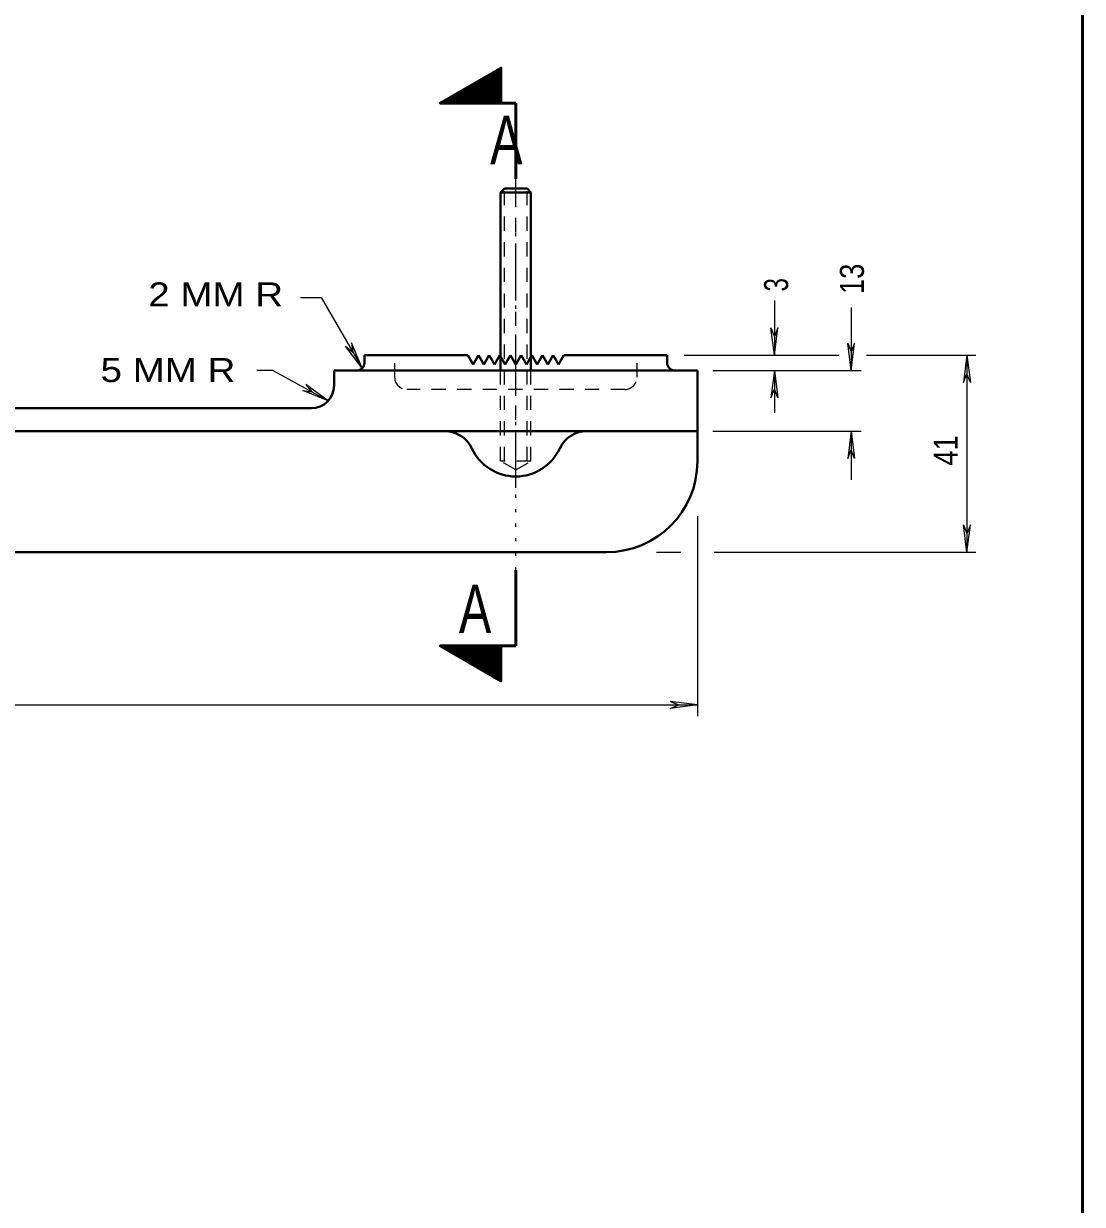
# Model space of a CAD drawing. Extents: x 312583 to 312854, y 144419 to 144597.
# Drawn here: x 312736.75 to 312770.25, y 144521.88 to 144559.26 of the extents above; entities that cross this region are included whole.
import ezdxf
from ezdxf.enums import TextEntityAlignment as Align

# ---------------------------------------------------------------- set-up
doc = ezdxf.new("R2010")
doc.units = 0
doc.header["$LTSCALE"] = 0.3
for name, pattern in [('DOTTED', [1.5, 0.3, -1.2]), ('LONG_DASH_SHORT_DASH', [9.9, 6, -1.2, 1.5, -1.2]), ('SHORT_DASHED', [2.7, 1.5, -1.2])]:
    doc.linetypes.add(name, pattern=pattern)
doc.layers.add('1', color=7, linetype='Continuous', lineweight=40)
doc.layers.add('2', color=7, linetype='Continuous', lineweight=13)

msp = doc.modelspace()

# ---------------------------------------------------------------- linework, layer by layer
at = {"layer": '1', "lineweight": 53}
for p, q in [((312770.2547, 144423.0156), (312770.2547, 144585.0846)), ((312751.851, 144556.7382), (312752.3263, 144556.7382)), ((312752.3263, 144554.3462), (312752.3263, 144556.7382)), ((312752.3263, 144541.9492), (312752.3263, 144539.5572)), ((312751.851, 144539.5572), (312752.3263, 144539.5572))]:
    msp.add_line(p, q, dxfattribs=at)
at = {"layer": '1', "lineweight": 35}
for p, q in [((312751.851, 144557.4358), (312751.6747, 144557.7425)), ((312751.851, 144557.4818), (312751.69, 144557.7502)), ((312751.851, 144557.5278), (312751.713, 144557.7655)), ((312751.851, 144557.5815), (312751.736, 144557.7732)), ((312751.851, 144557.6198), (312751.7513, 144557.7885)), ((312751.851, 144557.6735), (312751.7743, 144557.7962)), ((312751.851, 144557.7195), (312751.7973, 144557.8115)), ((312751.851, 144557.7732), (312751.8127, 144557.8268)), ((312751.851, 144557.8192), (312751.8357, 144557.8345)), ((312751.368, 144556.7382), (312751.0077, 144557.3592)), ((312751.391, 144556.7382), (312751.0307, 144557.3668)), ((312751.414, 144556.7382), (312751.046, 144557.3822)), ((312751.4447, 144556.7458), (312751.069, 144557.3898)), ((312751.4753, 144556.7382), (312751.092, 144557.4052)), ((312751.4983, 144556.7382), (312751.1073, 144557.4128)), ((312751.529, 144556.7382), (312751.1303, 144557.4282)), ((312751.5597, 144556.7382), (312751.1533, 144557.4435)), ((312751.5827, 144556.7382), (312751.1763, 144557.4512)), ((312751.6133, 144556.7382), (312751.1917, 144557.4665)), ((312751.644, 144556.7382), (312751.2147, 144557.4818)), ((312751.667, 144556.7458), (312751.2377, 144557.4895)), ((312751.6977, 144556.7458), (312751.253, 144557.5048)), ((312751.7207, 144556.7382), (312751.276, 144557.5125)), ((312751.7513, 144556.7382), (312751.299, 144557.5278)), ((312751.7743, 144556.7382), (312751.3143, 144557.5355)), ((312751.805, 144556.7382), (312751.3373, 144557.5508)), ((312751.8357, 144556.7382), (312751.3603, 144557.5585)), ((312751.851, 144556.7612), (312751.3757, 144557.5738)), ((312751.851, 144556.8148), (312751.4063, 144557.5815)), ((312751.851, 144556.8532), (312751.4217, 144557.5968)), ((312751.851, 144556.9068), (312751.4447, 144557.6045)), ((312751.851, 144556.9528), (312751.4677, 144557.6198)), ((312751.851, 144556.9988), (312751.483, 144557.6352)), ((312751.851, 144557.0448), (312751.506, 144557.6428)), ((312751.851, 144557.0985), (312751.529, 144557.6582)), ((312751.851, 144557.1445), (312751.5443, 144557.6735)), ((312751.851, 144557.1905), (312751.5673, 144557.6812)), ((312751.851, 144557.2442), (312751.5827, 144557.6965)), ((312751.851, 144557.2902), (312751.6057, 144557.7042)), ((312751.851, 144557.3362), (312751.6287, 144557.7195)), ((312751.851, 144557.3898), (312751.644, 144557.7272)), ((312750.5093, 144556.7382), (312750.3637, 144556.9912)), ((312750.5323, 144556.7382), (312750.379, 144556.9988)), ((312750.563, 144556.7382), (312750.4097, 144557.0142)), ((312750.586, 144556.7382), (312750.425, 144557.0218)), ((312750.6167, 144556.7382), (312750.448, 144557.0372)), ((312750.6473, 144556.7382), (312750.471, 144557.0448)), ((312750.6703, 144556.7382), (312750.4863, 144557.0602)), ((312750.701, 144556.7382), (312750.5093, 144557.0678)), ((312750.724, 144556.7382), (312750.5323, 144557.0832)), ((312750.7547, 144556.7382), (312750.5477, 144557.0985)), ((312750.7777, 144556.7382), (312750.5707, 144557.1062)), ((312750.8083, 144556.7382), (312750.5937, 144557.1215)), ((312750.839, 144556.7382), (312750.609, 144557.1368)), ((312750.8697, 144556.7382), (312750.632, 144557.1445)), ((312750.8927, 144556.7382), (312750.655, 144557.1598)), ((312750.9157, 144556.7382), (312750.678, 144557.1675)), ((312750.9463, 144556.7382), (312750.6933, 144557.1828)), ((312750.977, 144556.7382), (312750.7163, 144557.1905)), ((312751, 144556.7382), (312750.7393, 144557.2058)), ((312751.0307, 144556.7382), (312750.7547, 144557.2135)), ((312751.0613, 144556.7382), (312750.7777, 144557.2288)), ((312751.0843, 144556.7382), (312750.8007, 144557.2365)), ((312751.115, 144556.7382), (312750.816, 144557.2518)), ((312751.1457, 144556.7382), (312750.839, 144557.2595)), ((312751.1687, 144556.7382), (312750.862, 144557.2748)), ((312751.1993, 144556.7458), (312750.8773, 144557.2902)), ((312751.2223, 144556.7382), (312750.908, 144557.2978)), ((312751.253, 144556.7382), (312750.9233, 144557.3132)), ((312751.276, 144556.7382), (312750.9463, 144557.3208)), ((312751.3067, 144556.7382), (312750.9693, 144557.3362)), ((312751.3373, 144556.7382), (312750.9847, 144557.3438)), ((312749.9497, 144556.7382), (312749.9497, 144556.7535)), ((312749.9803, 144556.7382), (312749.9727, 144556.7612)), ((312750.011, 144556.7382), (312749.988, 144556.7765)), ((312750.034, 144556.7382), (312750.011, 144556.7842)), ((312750.0647, 144556.7382), (312750.034, 144556.7995)), ((312750.0877, 144556.7382), (312750.0493, 144556.8072)), ((312750.1183, 144556.7382), (312750.0723, 144556.8225)), ((312750.149, 144556.7382), (312750.0953, 144556.8302)), ((312750.1797, 144556.7382), (312750.1107, 144556.8455)), ((312750.2027, 144556.7382), (312750.1337, 144556.8532)), ((312750.2257, 144556.7382), (312750.1567, 144556.8685)), ((312750.2563, 144556.7382), (312750.1797, 144556.8762)), ((312750.2793, 144556.7382), (312750.195, 144556.8915)), ((312750.31, 144556.7382), (312750.218, 144556.9068)), ((312750.3407, 144556.7382), (312750.241, 144556.9145)), ((312750.3713, 144556.7382), (312750.2563, 144556.9298)), ((312750.3943, 144556.7382), (312750.2793, 144556.9452)), ((312750.425, 144556.7382), (312750.3023, 144556.9528)), ((312750.448, 144556.7382), (312750.3177, 144556.9682)), ((312750.4787, 144556.7382), (312750.3407, 144556.9758)), ((312749.9497, 144539.5572), (312749.9497, 144539.5418)), ((312749.9803, 144539.5572), (312749.9727, 144539.5342)), ((312750.011, 144539.5572), (312749.988, 144539.5188)), ((312750.034, 144539.5572), (312750.011, 144539.5112)), ((312750.0647, 144539.5572), (312750.034, 144539.4958)), ((312750.0877, 144539.5572), (312750.0493, 144539.4882)), ((312750.1183, 144539.5572), (312750.0723, 144539.4728)), ((312750.149, 144539.5572), (312750.0953, 144539.4652)), ((312750.1797, 144539.5572), (312750.1107, 144539.4498)), ((312750.2027, 144539.5572), (312750.1337, 144539.4422)), ((312750.2257, 144539.5572), (312750.1567, 144539.4268)), ((312750.2563, 144539.5572), (312750.1797, 144539.4192)), ((312750.2793, 144539.5572), (312750.195, 144539.4038)), ((312750.31, 144539.5572), (312750.218, 144539.3885)), ((312750.3407, 144539.5572), (312750.241, 144539.3808)), ((312750.3713, 144539.5572), (312750.2563, 144539.3655)), ((312750.3943, 144539.5572), (312750.2793, 144539.3502)), ((312750.425, 144539.5572), (312750.3023, 144539.3425)), ((312750.448, 144539.5572), (312750.3177, 144539.3272)), ((312750.4787, 144539.5572), (312750.3407, 144539.3195)), ((312750.5093, 144539.5572), (312750.3637, 144539.3042)), ((312750.5323, 144539.5572), (312750.379, 144539.2965)), ((312750.563, 144539.5572), (312750.4097, 144539.2812)), ((312750.586, 144539.5572), (312750.425, 144539.2735)), ((312750.6167, 144539.5572), (312750.448, 144539.2582)), ((312750.6473, 144539.5572), (312750.471, 144539.2505)), ((312750.6703, 144539.5572), (312750.4863, 144539.2352)), ((312750.701, 144539.5572), (312750.5093, 144539.2275)), ((312750.724, 144539.5572), (312750.5323, 144539.2122)), ((312750.7547, 144539.5572), (312750.5477, 144539.1968)), ((312750.7777, 144539.5572), (312750.5707, 144539.1892)), ((312750.8083, 144539.5572), (312750.5937, 144539.1738)), ((312750.839, 144539.5572), (312750.609, 144539.1585)), ((312750.8697, 144539.5572), (312750.632, 144539.1508)), ((312750.8927, 144539.5572), (312750.655, 144539.1355)), ((312750.9157, 144539.5572), (312750.678, 144539.1278)), ((312750.9463, 144539.5572), (312750.6933, 144539.1125)), ((312750.977, 144539.5572), (312750.7163, 144539.1048)), ((312751, 144539.5572), (312750.7393, 144539.0895)), ((312751.0307, 144539.5572), (312750.7547, 144539.0818)), ((312751.0613, 144539.5572), (312750.7777, 144539.0665)), ((312751.0843, 144539.5572), (312750.8007, 144539.0588)), ((312751.115, 144539.5572), (312750.816, 144539.0435)), ((312751.1457, 144539.5572), (312750.839, 144539.0358)), ((312751.1687, 144539.5572), (312750.862, 144539.0205)), ((312751.1993, 144539.5495), (312750.8773, 144539.0052)), ((312751.2223, 144539.5572), (312750.908, 144538.9975)), ((312751.253, 144539.5572), (312750.9233, 144538.9822)), ((312751.276, 144539.5572), (312750.9463, 144538.9745)), ((312751.3067, 144539.5572), (312750.9693, 144538.9592)), ((312751.3373, 144539.5572), (312750.9847, 144538.9515)), ((312751.368, 144539.5572), (312751.0077, 144538.9362)), ((312751.391, 144539.5572), (312751.0307, 144538.9285)), ((312751.414, 144539.5572), (312751.046, 144538.9132)), ((312751.4447, 144539.5495), (312751.069, 144538.9055)), ((312751.4753, 144539.5572), (312751.092, 144538.8902)), ((312751.4983, 144539.5572), (312751.1073, 144538.8825)), ((312751.529, 144539.5572), (312751.1303, 144538.8672)), ((312751.5597, 144539.5572), (312751.1533, 144538.8518)), ((312751.5827, 144539.5572), (312751.1763, 144538.8442)), ((312751.6133, 144539.5572), (312751.1917, 144538.8288)), ((312751.644, 144539.5572), (312751.2147, 144538.8135)), ((312751.667, 144539.5495), (312751.2377, 144538.8058)), ((312751.6977, 144539.5495), (312751.253, 144538.7905)), ((312751.7207, 144539.5572), (312751.276, 144538.7828)), ((312751.7513, 144539.5572), (312751.299, 144538.7675)), ((312751.7743, 144539.5572), (312751.3143, 144538.7598)), ((312751.805, 144539.5572), (312751.3373, 144538.7445)), ((312751.8357, 144539.5572), (312751.3603, 144538.7368)), ((312751.851, 144539.5342), (312751.3757, 144538.7215)), ((312751.851, 144539.4805), (312751.4063, 144538.7138)), ((312751.851, 144539.4422), (312751.4217, 144538.6985)), ((312751.851, 144539.3885), (312751.4447, 144538.6908)), ((312751.851, 144539.3425), (312751.4677, 144538.6755)), ((312751.851, 144539.2965), (312751.483, 144538.6602)), ((312751.851, 144539.2505), (312751.506, 144538.6525)), ((312751.851, 144539.1968), (312751.529, 144538.6372)), ((312751.851, 144539.1508), (312751.5443, 144538.6218)), ((312751.851, 144539.1048), (312751.5673, 144538.6142)), ((312751.851, 144539.0512), (312751.5827, 144538.5988)), ((312751.851, 144539.0052), (312751.6057, 144538.5912)), ((312751.851, 144538.9592), (312751.6287, 144538.5758)), ((312751.851, 144538.9055), (312751.644, 144538.5682)), ((312751.851, 144538.8595), (312751.6747, 144538.5528)), ((312751.851, 144538.8135), (312751.69, 144538.5452)), ((312751.851, 144538.7675), (312751.713, 144538.5298)), ((312751.851, 144538.7138), (312751.736, 144538.5222)), ((312751.851, 144538.6755), (312751.7513, 144538.5068)), ((312751.851, 144538.6218), (312751.7743, 144538.4992)), ((312751.851, 144538.5758), (312751.7973, 144538.4838)), ((312751.851, 144538.5222), (312751.8127, 144538.4685)), ((312751.851, 144538.4762), (312751.8357, 144538.4608))]:
    msp.add_line(p, q, dxfattribs=at)
at = {"layer": '1', "linetype": 'DOTTED', "lineweight": 13}
msp.add_line((312752.3263, 144541.9492), (312752.3263, 144554.8215), dxfattribs=at)
at = {"layer": '1', "linetype": 'LONG_DASH_SHORT_DASH', "lineweight": 13}
msp.add_line((312752.3263, 144544.5558), (312752.3263, 144554.5378), dxfattribs=at)
at = {"layer": '1'}
for p, q in [((312751.8433, 144553.9092), (312751.966, 144554.0318)), ((312752.679, 144554.0318), (312751.966, 144554.0318)), ((312752.8017, 144553.9092), (312752.679, 144554.0318)), ((312752.8017, 144553.9092), (312751.8433, 144553.9092)), ((312751.8433, 144548.2742), (312751.8433, 144553.9092)), ((312752.8017, 144548.2742), (312752.8017, 144553.9092)), ((312747.5347, 144548.5195), (312747.5347, 144548.7572)), ((312750.8083, 144548.7572), (312747.5347, 144548.7572)), ((312750.977, 144548.4658), (312750.8083, 144548.7572)), ((312750.977, 144548.4658), (312751.1457, 144548.7572)), ((312751.3143, 144548.4658), (312751.1457, 144548.7572)), ((312751.3143, 144548.4658), (312751.483, 144548.7572)), ((312751.6517, 144548.4658), (312751.483, 144548.7572)), ((312751.6517, 144548.4658), (312751.8203, 144548.7572)), ((312751.989, 144548.4658), (312751.8203, 144548.7572)), ((312751.989, 144548.4658), (312752.1577, 144548.7572)), ((312752.3263, 144548.4658), (312752.1577, 144548.7572)), ((312752.3263, 144548.4658), (312752.495, 144548.7572)), ((312752.6637, 144548.4658), (312752.495, 144548.7572)), ((312752.6637, 144548.4658), (312752.8323, 144548.7572)), ((312753.001, 144548.4658), (312752.8323, 144548.7572)), ((312753.001, 144548.4658), (312753.1697, 144548.7572)), ((312753.3383, 144548.4658), (312753.1697, 144548.7572)), ((312753.3383, 144548.4658), (312753.507, 144548.7572)), ((312753.6757, 144548.4658), (312753.507, 144548.7572)), ((312753.6757, 144548.4658), (312753.8443, 144548.7572)), ((312757.118, 144548.7572), (312753.8443, 144548.7572)), ((312757.118, 144548.5195), (312757.118, 144548.7572)), ((312746.5763, 144547.7988), (312746.5763, 144548.2742)), ((312758.0763, 144548.2742), (312746.5763, 144548.2742)), ((312758.0763, 144545.3992), (312758.0763, 144548.2742)), ((312692.9097, 144547.0782), (312745.8557, 144547.0782)), ((312692.9097, 144546.3575), (312758.0763, 144546.3575)), ((312695.7847, 144542.5242), (312755.2013, 144542.5242))]:
    msp.add_line(p, q, dxfattribs=at)
at = {"layer": '1', "linetype": 'SHORT_DASHED', "lineweight": 25}
for p, q in [((312751.966, 144545.4068), (312751.966, 144554.0318)), ((312752.679, 144545.4068), (312752.679, 144554.0318)), ((312748.493, 144548.0595), (312748.493, 144548.7572)), ((312756.1597, 144548.0595), (312756.1597, 144548.7572)), ((312751.8433, 144545.4068), (312751.8433, 144548.2742)), ((312752.8017, 144545.4068), (312752.8017, 144548.2742)), ((312755.7763, 144547.6762), (312748.8763, 144547.6762)), ((312752.8017, 144545.4068), (312751.8433, 144545.4068)), ((312752.3263, 144545.1308), (312751.8433, 144545.4068)), ((312752.3263, 144545.1308), (312752.8017, 144545.4068))]:
    msp.add_line(p, q, dxfattribs=at)
at = {"layer": '1', "lineweight": 53}
for points in [[(312751.851, 144556.7382), (312751.851, 144557.8498), (312749.9343, 144556.7382)], [(312751.851, 144539.5572), (312751.851, 144538.4455), (312749.9343, 144539.5572)]]:
    msp.add_lwpolyline(points, close=True, dxfattribs=at)
at = {"layer": '1'}
for centre, radius, start, end in [((312747.2913, 144548.5137), 0.2396, 270, 0), ((312757.3538, 144548.5137), 0.2396, 180, 270), ((312745.8538, 144547.7969), 0.7188, 270, 0), ((312750.0648, 144545.3992), 0.9583, 25.029, 90), ((312754.5802, 144545.3992), 0.9583, 90, 154.971), ((312752.3225, 144546.4533), 1.5333, 205.029, 334.971), ((312755.1975, 144545.3992), 2.875, 270, 0)]:
    msp.add_arc(centre, radius, start, end, dxfattribs=at)
at = {"layer": '1', "linetype": 'SHORT_DASHED', "lineweight": 25}
for centre, start, end in [((312748.8725, 144548.0595), 180, 270), ((312755.7725, 144548.0595), 270, 0)]:
    msp.add_arc(centre, 0.3833, start, end, dxfattribs=at)
at = {"layer": '2'}
for p, q in [((312745.5107, 144550.5895), (312746.1623, 144550.5895)), ((312746.1623, 144550.5895), (312747.4657, 144548.3508)), ((312760.5067, 144550.4863), (312760.5067, 144548.7572)), ((312762.937, 144550.2735), (312762.937, 144548.2742)), ((312760.3993, 144549.6235), (312760.5067, 144549.3475)), ((312760.5067, 144548.7572), (312760.3993, 144549.6235)), ((312760.614, 144549.6235), (312760.5067, 144549.3475)), ((312760.5067, 144548.7572), (312760.614, 144549.6235)), ((312747.1207, 144549.1558), (312747.1667, 144548.8568)), ((312747.4657, 144548.3508), (312747.1207, 144549.1558)), ((312762.8297, 144549.1405), (312762.937, 144548.8645)), ((312762.937, 144548.2742), (312762.8297, 144549.1405)), ((312763.0443, 144549.1405), (312762.937, 144548.8645)), ((312762.937, 144548.2742), (312763.0443, 144549.1405)), ((312746.9367, 144549.0485), (312747.1667, 144548.8568)), ((312747.4657, 144548.3508), (312746.9367, 144549.0485)), ((312757.647, 144548.7572), (312762.546, 144548.7572)), ((312763.42, 144548.7572), (312766.8853, 144548.7572)), ((312766.6017, 144548.7572), (312766.4943, 144547.8908)), ((312766.6017, 144548.7572), (312766.6017, 144542.5242)), ((312766.6017, 144548.7572), (312766.709, 144547.8908)), ((312758.5593, 144548.2742), (312763.2513, 144548.2742)), ((312760.5067, 144548.2742), (312760.3993, 144547.4078)), ((312760.5067, 144548.2742), (312760.5067, 144546.9325)), ((312760.5067, 144548.2742), (312760.614, 144547.4078)), ((312766.4943, 144547.8908), (312766.6017, 144548.1668)), ((312766.709, 144547.8908), (312766.6017, 144548.1668)), ((312745.5797, 144547.6378), (312745.871, 144547.5995)), ((312746.3847, 144547.3158), (312745.5797, 144547.6378)), ((312745.6793, 144547.8295), (312745.871, 144547.5995)), ((312746.3847, 144547.3158), (312745.6793, 144547.8295)), ((312760.3993, 144547.4078), (312760.5067, 144547.6838)), ((312760.614, 144547.4078), (312760.5067, 144547.6838)), ((312758.5593, 144546.3575), (312763.2513, 144546.3575)), ((312762.937, 144546.3575), (312762.8297, 144545.4912)), ((312762.937, 144546.3575), (312762.937, 144544.8165)), ((312762.937, 144546.3575), (312763.0443, 144545.4912)), ((312762.8297, 144545.4912), (312762.937, 144545.7672)), ((312763.0443, 144545.4912), (312762.937, 144545.7672)), ((312758.0763, 144543.6665), (312758.0763, 144537.3338)), ((312766.4943, 144543.3905), (312766.6017, 144543.1145)), ((312766.6017, 144542.5242), (312766.4943, 144543.3905)), ((312766.709, 144543.3905), (312766.6017, 144543.1145)), ((312766.6017, 144542.5242), (312766.709, 144543.3905)), ((312756.773, 144542.5242), (312757.5473, 144542.5242)), ((312758.5977, 144542.5242), (312766.8853, 144542.5242)), ((312692.9097, 144537.6865), (312758.0763, 144537.6865)), ((312757.21, 144537.7938), (312757.486, 144537.6865)), ((312758.0763, 144537.6865), (312757.21, 144537.7938)), ((312757.21, 144537.5792), (312757.486, 144537.6865)), ((312758.0763, 144537.6865), (312757.21, 144537.5792))]:
    msp.add_line(p, q, dxfattribs=at)
msp.add_lwpolyline([(312744.1307, 144548.2895), (312744.6213, 144548.2895), (312746.3847, 144547.3158)], dxfattribs=at)

# ---------------------------------------------------------------- texts
at = {"layer": '1', "width": 0.75}
for p in [(312752.0235, 144554.8062), (312751.0345, 144539.9635)]:
    msp.add_text('A', height=1.533, dxfattribs=at).set_placement(p, align=Align.CENTER)
at = {"layer": '2'}
for s, width, p in [('13', 0.85, (312763.3401, 144550.6956)), ('3', 0.75, (312760.9423, 144550.7768)), ('41', 0.85, (312766.3091, 144545.2654))]:
    msp.add_text(s, height=0.76, rotation=90, dxfattribs=dict(at, width=width)).set_placement(p)
at = {"layer": '2', "width": 1.2}
for s, p in [('2 MM R', (312740.6903, 144550.3034)), ('5 MM R', (312739.1812, 144547.9095))]:
    msp.add_text(s, height=0.76, dxfattribs=at).set_placement(p)

doc.saveas('drawing.dxf')
